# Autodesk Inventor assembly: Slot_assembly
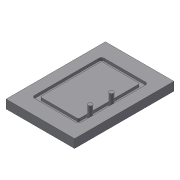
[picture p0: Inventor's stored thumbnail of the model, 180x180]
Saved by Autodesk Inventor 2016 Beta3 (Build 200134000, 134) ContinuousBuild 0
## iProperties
Created: 2016-03
Part Number: Slot_assembly
Document SubType Name: Assembly
Designer: Gaurav
Author: Gaurav
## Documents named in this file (3)
- D:\My Data\Books_Final Books\Autodesk Inventor 2015_resources\Chapter 7\Slot\Slot_assembly.iam
- D:\My Data\Books_Final Books\Autodesk Inventor 2015_resources\Chapter 7\Slot\Base.ipt
- D:\My Data\Books_Final Books\Autodesk Inventor 2015_resources\Chapter 7\Slot\follower.ipt
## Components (3 placed, 2 different names)
1. Base:1 — Mate:1, Mate:2, Tangent:1, Mate:3, Tangent:2, Mate:4, Mate:5
2. follower:1 — Mate:2, Tangent:1
3. follower:2 — Mate:3, Tangent:2
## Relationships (7: Mate 5, Tangent 2)
- Mate:1: Base:1
- Mate:2: Base:1 ↔ follower:1
- Tangent:1: Base:1 ↔ follower:1
- Mate:3: Base:1 ↔ follower:2
- Tangent:2: Base:1 ↔ follower:2
- Mate:4: Base:1
- Mate:5: Base:1
